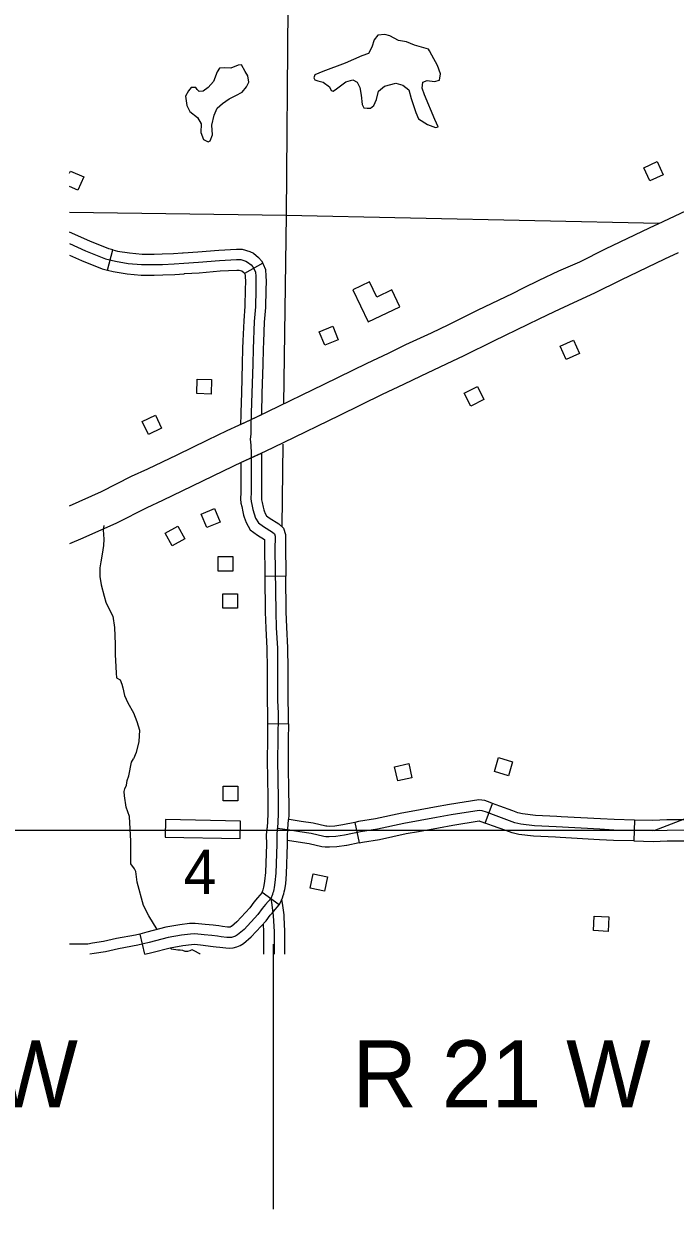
# Model space of a CAD drawing. Extents: x 61396 to 64680, y 55472 to 57605.
# Drawn here: x 61905.3 to 62051.4, y 55666.6 to 55932.3 of the extents above; entities that cross this region are included whole.
import ezdxf

# ---------------------------------------------------------------- set-up
doc = ezdxf.new("R2010")
doc.units = 0
for name, color, linetype in [('15', 7, 'Continuous'), ('31', 7, 'Continuous'), ('32', 7, 'Continuous'), ('35', 7, 'Continuous'), ('4', 7, 'Continuous'), ('5', 7, 'Continuous'), ('56', 7, 'Continuous'), ('57', 7, 'Continuous'), ('58', 7, 'Continuous'), ('Default', 7, 'Continuous'), ('R_Border Notes', 7, 'Continuous')]:
    doc.layers.add(name, color=color, linetype=linetype)

msp = doc.modelspace()

# ---------------------------------------------------------------- linework, layer by layer
at = {"layer": '15'}
for points in [[(61915.57, 55824.22), (61922.72, 55827.44), (61929.47, 55830.86), (61933.08, 55832.55), (61939.65, 55835.69), (61946.55, 55839.02), (61950.87, 55841.13), (61956.12, 55843.51), (61960.02, 55845.38), (61972.67, 55851.5), (61982.27, 55856.25), (61987.09, 55858.48), (61990.95, 55860.38), (61996.73, 55863.04), (62000.57, 55864.87), (62007.2, 55868.15), (62014.85, 55871.86), (62017.36, 55873.12), (62020.84, 55874.81), (62025.31, 55876.88), (62029.96, 55878.95), (62035.75, 55881.8), (62045.62, 55886.55), (62048.7, 55887.99), (62053.87, 55890.44)], [(62052.03, 55880.92), (62048.98, 55879.49), (62039.17, 55874.78), (62033.27, 55871.87), (62028.54, 55869.77), (62024.19, 55867.75), (62020.81, 55866.11), (62018.3, 55864.85), (62010.64, 55861.14), (62003.99, 55857.84), (62000.04, 55855.96), (61994.31, 55853.33), (61990.46, 55851.43), (61985.64, 55849.2), (61976.11, 55844.48), (61963.42, 55838.35), (61959.43, 55836.42), (61954.19, 55834.06), (61949.97, 55832), (61943.04, 55828.65), (61936.43, 55825.48), (61932.89, 55823.83), (61926.09, 55820.39), (61918.55, 55817), (61915.57, 55815.71)]]:
    msp.add_lwpolyline(points, dxfattribs=at)
at = {"layer": '31'}
for p, q in [((61924.07, 55877.07), (61925.22, 55881.61)), ((61924.07, 55877.07), (61924.07, 55877.07)), ((61958.86, 55878.64), (61954.77, 55876.34)), ((61953.94, 55833.94), (61958.63, 55836.06)), ((61964.03, 55808.47), (61959.34, 55808.42)), ((61959.95, 55775.48), (61964.63, 55775.43)), ((61964.63, 55775.43), (61964.63, 55775.43)), ((62008.79, 55753.15), (62010.43, 55757.55)), ((61979.56, 55753.32), (61980.53, 55748.73)), ((62042.21, 55753.84), (62042.1, 55749.15)), ((61962.52, 55734.83), (61958.74, 55737.62)), ((61931.3, 55728.3), (61932.38, 55723.76))]:
    msp.add_line(p, q, dxfattribs=at)
for points in [[(61925.22, 55881.61), (61924.34, 55881.83), (61920.08, 55883.54), (61915.57, 55885.59)], [(61915.57, 55883.01), (61919.16, 55881.39), (61923.61, 55879.6), (61925.82, 55879.04), (61928.73, 55878.58), (61931.71, 55878.3), (61934.51, 55878.3), (61936.37, 55878.34), (61939, 55878.44), (61941.17, 55878.62), (61944.47, 55878.83), (61949.2, 55879.21), (61953.02, 55879.42), (61953.93, 55879.42), (61955.09, 55879.07), (61955.48, 55878.86), (61956.28, 55878.23), (61956.63, 55877.81), (61956.95, 55877.25), (61957.26, 55876.59), (61957.3, 55875.71), (61957.33, 55874.52), (61957.3, 55872.66), (61957.23, 55868.84), (61956.95, 55865.55), (61956.7, 55859.45), (61956.63, 55856.01), (61956.42, 55849.49), (61956.31, 55845.09), (61956.23, 55842.25), (61956.2, 55841.99), (61956.2, 55841.16), (61956.17, 55840.28), (61956.09, 55839.2)], [(61915.57, 55880.44), (61918.24, 55879.23), (61922.89, 55877.37), (61924.07, 55877.07)], [(61925.22, 55881.61), (61926.29, 55881.34), (61929.02, 55880.91), (61931.82, 55880.65), (61934.49, 55880.65), (61936.3, 55880.68), (61938.86, 55880.78), (61940.86, 55880.94)], [(61940.86, 55880.94), (61941.01, 55880.96), (61944.3, 55881.17), (61949.04, 55881.55), (61952.96, 55881.77), (61954.28, 55881.77), (61956, 55881.25), (61956.77, 55880.83), (61957.92, 55879.92), (61958.57, 55879.15), (61958.86, 55878.64)], [(61924.07, 55877.07), (61925.35, 55876.74), (61928.44, 55876.26), (61931.6, 55875.96), (61934.54, 55875.96), (61936.44, 55875.99), (61939.14, 55876.1), (61941.24, 55876.27)], [(61941.24, 55876.27), (61941.34, 55876.28), (61944.64, 55876.49), (61949.36, 55876.88), (61953.09, 55877.08), (61953.59, 55877.08), (61954.18, 55876.9), (61954.18, 55876.9), (61954.64, 55876.54), (61954.69, 55876.48), (61954.77, 55876.34)], [(61959.11, 55861.02), (61959.29, 55865.4), (61959.57, 55868.72), (61959.64, 55872.62), (61959.68, 55874.53), (61959.64, 55875.79), (61959.59, 55877.16), (61959.03, 55878.33), (61958.86, 55878.64)], [(61954.77, 55876.34), (61954.86, 55876.17), (61954.94, 55876.01), (61954.96, 55875.63), (61954.99, 55874.51), (61954.95, 55872.7), (61954.89, 55868.96), (61954.61, 55865.69), (61954.43, 55861.21)], [(61954.43, 55861.21), (61954.36, 55859.52), (61954.29, 55856.07), (61954.08, 55849.56), (61953.97, 55845.15), (61953.96, 55844.69)], [(61958.65, 55844.72), (61958.66, 55845.03), (61958.76, 55849.43), (61958.97, 55855.95), (61959.04, 55859.38), (61959.11, 55861.02)], [(61953.96, 55844.69), (61953.9, 55842.5), (61956.12, 55843.51), (61958.65, 55844.72)], [(61956.09, 55839.2), (61956.21, 55837.87), (61956.28, 55835.96), (61956.28, 55832.57), (61956.28, 55827.22), (61956.24, 55825.87), (61956.31, 55825.24), (61956.45, 55824.54), (61956.67, 55823.44), (61956.94, 55822.42), (61957.28, 55821.52), (61957.89, 55820.43), (61959.03, 55819.59), (61961.09, 55818.35), (61961.49, 55817.98), (61961.65, 55817.48), (61961.62, 55814.41), (61961.67, 55809.81), (61961.78, 55800.48), (61961.91, 55796.93), (61962.16, 55792.34), (61962.19, 55788.15), (61962.22, 55780.59), (61962.31, 55777.8), (61962.25, 55771.83), (61962.22, 55767.34), (61962.34, 55758.6), (61962.37, 55755.08), (61962.18, 55751.92)], [(61958.63, 55836.06), (61958.63, 55832.57), (61958.63, 55827.18), (61958.58, 55825.96), (61958.62, 55825.61), (61958.75, 55825), (61958.96, 55823.97), (61959.12, 55823.37)], [(61953.94, 55833.94), (61953.94, 55832.57), (61953.94, 55827.26), (61953.89, 55825.78), (61953.99, 55824.87), (61954.16, 55824.07), (61954.39, 55822.92), (61954.58, 55822.18)], [(61954.58, 55822.18), (61954.7, 55821.71), (61955.15, 55820.53), (61956.09, 55818.84), (61957.73, 55817.64), (61959.3, 55816.7), (61959.28, 55814.41), (61959.33, 55809.78), (61959.34, 55808.42)], [(61959.12, 55823.37), (61959.18, 55823.14), (61959.41, 55822.51), (61959.69, 55822.02), (61960.33, 55821.55), (61962.51, 55820.23), (61963.54, 55819.28), (61963.99, 55817.83), (61963.96, 55814.42), (61964.02, 55809.84), (61964.03, 55808.47)], [(61959.34, 55808.42), (61959.44, 55800.42), (61959.57, 55796.83), (61959.82, 55792.27), (61959.82, 55791.94)], [(61964.51, 55791.97), (61964.5, 55792.41), (61964.25, 55797.04), (61964.12, 55800.53), (61964.03, 55808.47)], [(61959.82, 55791.94), (61959.85, 55788.14), (61959.88, 55780.55), (61959.97, 55777.78), (61959.95, 55775.48)], [(61964.63, 55775.43), (61964.66, 55777.83), (61964.57, 55780.64), (61964.54, 55788.16), (61964.51, 55791.97)], [(61959.95, 55775.48), (61959.91, 55771.85), (61959.88, 55767.33), (61960, 55758.93)], [(61964.63, 55775.43), (61964.6, 55771.81), (61964.57, 55767.34), (61964.68, 55758.99)], [(61960, 55758.93), (61960, 55758.57), (61960.03, 55755.14), (61959.84, 55752.06)], [(61964.68, 55758.99), (61964.69, 55758.62), (61964.72, 55755.01), (61964.65, 55753.94)], [(62010.43, 55757.55), (62009.84, 55757.77), (62008.66, 55758.21), (62007.33, 55758.37), (62000.72, 55757.34), (61997.42, 55756.71), (61993.01, 55755.92)], [(62025.81, 55754.59), (62024.79, 55754.65), (62020.01, 55754.88), (62017.13, 55755.25), (62016.09, 55755.49), (62014.99, 55755.88), (62012.01, 55756.96), (62010.43, 55757.55)], [(62056.34, 55751.56), (62049.53, 55751.52), (62046.38, 55751.4), (62037.62, 55751.6), (62034.5, 55751.76), (62024.67, 55752.31), (62019.8, 55752.55), (62016.72, 55752.94), (62015.44, 55753.23), (62014.2, 55753.68), (62011.2, 55754.76), (62009.02, 55755.57), (62008.1, 55755.91), (62007.37, 55756), (62001.11, 55755.03), (61997.85, 55754.41), (61990.55, 55753.09), (61984.62, 55751.79), (61980.81, 55751.19), (61977.24, 55750.43), (61975.29, 55750.14), (61973.8, 55750.08), (61973.04, 55750.1), (61972.57, 55750.16), (61969.74, 55750.84), (61967.17, 55751.22), (61964.96, 55751.54), (61962.18, 55751.92)], [(61993.01, 55755.92), (61990.08, 55755.39), (61984.18, 55754.09), (61980.38, 55753.49), (61979.56, 55753.32)], [(61964.44, 55749.24), (61964.42, 55750.31), (61964.52, 55751.76), (61964.65, 55753.94)], [(61976.82, 55752.74), (61975.07, 55752.47), (61973.78, 55752.42), (61973.22, 55752.44), (61972.99, 55752.47), (61970.19, 55753.14), (61967.51, 55753.54), (61965.28, 55753.86), (61964.65, 55753.94)], [(61979.56, 55753.32), (61976.82, 55752.74)], [(61993.84, 55751.3), (61998.28, 55752.11), (62001.51, 55752.72), (62007.41, 55753.64), (62007.54, 55753.62), (62008.2, 55753.38), (62008.79, 55753.15)], [(62025.54, 55749.91), (62024.54, 55749.97), (62019.59, 55750.21), (62016.32, 55750.63), (62014.78, 55750.98), (62013.4, 55751.47), (62010.39, 55752.56), (62008.79, 55753.15)], [(62042.21, 55753.84), (62037.7, 55753.94), (62034.63, 55754.1), (62025.81, 55754.59)], [(62058.81, 55753.61), (62058.2, 55753.66), (62056.51, 55753.9), (62049.48, 55753.86), (62046.36, 55753.75), (62042.21, 55753.84)], [(61958.74, 55737.62), (61958.92, 55738.03), (61958.98, 55738.23), (61959.06, 55738.5), (61959.13, 55738.82), (61959.22, 55739.2), (61959.37, 55740.11), (61959.55, 55742.11), (61959.76, 55748.43), (61959.73, 55750.42), (61959.84, 55752.07)], [(61960.74, 55736.35), (61961.13, 55737.21), (61961.24, 55737.59), (61961.33, 55737.92), (61961.41, 55738.29), (61961.52, 55738.75), (61961.69, 55739.81), (61961.89, 55741.97), (61962.11, 55748.41), (61962.08, 55750.37), (61962.18, 55751.92)], [(61980.53, 55748.73), (61981.24, 55748.88), (61985.05, 55749.48), (61991.01, 55750.79), (61993.84, 55751.3)], [(62042.1, 55749.15), (62037.53, 55749.26), (62034.38, 55749.42), (62025.54, 55749.91)], [(61962.52, 55734.83), (61962.88, 55735.39), (61963.33, 55736.39), (61963.49, 55736.96), (61963.6, 55737.34), (61963.7, 55737.76), (61963.82, 55738.3), (61964.02, 55739.52), (61964.23, 55741.82), (61964.45, 55748.39), (61964.44, 55749.24)], [(61977.73, 55748.14), (61977.65, 55748.12), (61975.51, 55747.8), (61973.81, 55747.73), (61972.86, 55747.76), (61972.15, 55747.85), (61969.29, 55748.53), (61966.83, 55748.91), (61964.44, 55749.24)], [(61980.53, 55748.73), (61977.73, 55748.14)], [(62042.1, 55749.15), (62046.39, 55749.06), (62049.58, 55749.18), (62056.18, 55749.21), (62057.68, 55748.99), (62058.46, 55748.94)], [(61960.74, 55736.35), (61959.5, 55734.91), (61958.72, 55734), (61957.81, 55732.71), (61954.68, 55729.35), (61953.21, 55728.09), (61952.77, 55727.84), (61952.32, 55727.65), (61951.86, 55727.52), (61951.46, 55727.5), (61950.8, 55727.52), (61949.54, 55727.67), (61948.7, 55727.79), (61947.44, 55727.94), (61945.74, 55728.14), (61943.67, 55728.34), (61942.68, 55728.29), (61940.62, 55728.04), (61937.65, 55727.52), (61933.44, 55726.41), (61930.83, 55725.78), (61926.54, 55724.96), (61923.6, 55724.34), (61921.09, 55723.92), (61920.12, 55723.76)], [(61958.74, 55737.62), (61957.73, 55736.43), (61956.87, 55735.44), (61955.99, 55734.19), (61953.06, 55731.04), (61951.85, 55730.01), (61951.74, 55729.95), (61951.54, 55729.87), (61951.48, 55729.85), (61951.44, 55729.85), (61950.97, 55729.86), (61949.84, 55729.99), (61949, 55730.11), (61948.34, 55730.19)], [(61947.79, 55725.54), (61948.4, 55725.46), (61949.24, 55725.34), (61950.63, 55725.18), (61951.48, 55725.16), (61952.25, 55725.19), (61953.1, 55725.44), (61953.81, 55725.73), (61954.57, 55726.17), (61956.31, 55727.65), (61959.64, 55731.23), (61960.57, 55732.55), (61961.28, 55733.38), (61962.52, 55734.83)], [(61931.3, 55728.3), (61930.34, 55728.08), (61926.08, 55727.26), (61923.16, 55726.64), (61920.7, 55726.23), (61919.67, 55726.06), (61919.13, 55726.06), (61917.7, 55726.03), (61916.55, 55726.04), (61915.58, 55726.05)], [(61948.34, 55730.19), (61947.72, 55730.26), (61945.99, 55730.47), (61943.72, 55730.69), (61942.47, 55730.63), (61940.28, 55730.36), (61937.14, 55729.81), (61932.87, 55728.68), (61931.3, 55728.3)], [(61915.58, 55726.05), (61915.57, 55726.05)], [(61932.44, 55723.76), (61934.01, 55724.13), (61938.15, 55725.23), (61940.97, 55725.72), (61942.88, 55725.95), (61943.62, 55725.99), (61945.49, 55725.81), (61947.16, 55725.61), (61947.79, 55725.54)]]:
    msp.add_lwpolyline(points, dxfattribs=at)
at = {"layer": '32'}
for points in [[(61961.49, 55723.76), (61961.49, 55728.87), (61961.32, 55732.41), (61960.99, 55734.84), (61960.74, 55736.35)], [(61963.68, 55732.07), (61963.65, 55732.63), (61963.3, 55735.19), (61963.17, 55736.03)], [(61963.84, 55723.76), (61963.84, 55728.93), (61963.68, 55732.07)], [(61959.15, 55723.76), (61959.15, 55728.81), (61959.06, 55730.61)]]:
    msp.add_lwpolyline(points, dxfattribs=at)
at = {"layer": '35'}
for points in [[(61996.03, 55926.6), (61992.91, 55927.5), (61991.08, 55928.21), (61989.35, 55928.53), (61987.38, 55929.55), (61986.28, 55929.86), (61984.71, 55929.71), (61983.84, 55928.68), (61983.37, 55927.03), (61982.58, 55925.61), (61981.09, 55925.06), (61977.39, 55923.41), (61972.36, 55921.6), (61970.55, 55920.82), (61970.31, 55920.19), (61970.55, 55919.71), (61971.26, 55919.48), (61972.44, 55919.16), (61973.85, 55918.14), (61974.24, 55917.35), (61974.64, 55917.2), (61975.43, 55917.67), (61977.47, 55919.24), (61979.04, 55919.71), (61980.07, 55919.16), (61980.62, 55917.98), (61980.93, 55916.25), (61981.17, 55914.21), (61981.56, 55913.42), (61982.27, 55913.34), (61983.06, 55913.34), (61983.76, 55913.97), (61984.39, 55915.31), (61984.87, 55917.2), (61986.2, 55918.3), (61988.72, 55918.93), (61990.3, 55918.53), (61991.63, 55917.43), (61992.18, 55915.55), (61993.21, 55912.4), (61993.84, 55910.98), (61995.8, 55909.72), (61997.61, 55909.02), (61998.24, 55909.17), (61997.46, 55910.83), (61995.17, 55916.33), (61994.62, 55917.83), (61994.78, 55919.16), (61995.72, 55919.56), (61997.38, 55919.32), (61998.48, 55919.64), (61998.71, 55921.05), (61998.08, 55922.94), (61996.83, 55925.22), (61996.27, 55926.17)], [(61954.94, 55921.61), (61954.09, 55923.08), (61953.35, 55923.02), (61951.75, 55922.34), (61950.4, 55922.41), (61949.18, 55922.34), (61948.69, 55921.49), (61947.83, 55919.34), (61946.6, 55917.99), (61945.5, 55917.13), (61944.58, 55917.07), (61944.15, 55917.56), (61943.84, 55917.99), (61942.86, 55917.99), (61942.24, 55917.25), (61941.57, 55916.03), (61941.88, 55913.94), (61942.49, 55912.59), (61944.21, 55911.3), (61945.07, 55909.83), (61945, 55907.87), (61945.62, 55906.33), (61946.6, 55905.84), (61947.09, 55906.03), (61947.58, 55907.38), (61947.46, 55909.58), (61948.01, 55911.79), (61948.69, 55913.33), (61949.85, 55914.43), (61951.32, 55915.47), (61952.86, 55916.21), (61954.27, 55916.95), (61955.25, 55918.11), (61955.74, 55919.15), (61955.56, 55920.57)]]:
    msp.add_lwpolyline(points, close=True, dxfattribs=at)
for points in [[(61923.24, 55819.85), (61923.12, 55818.85), (61923.27, 55816.75), (61923.19, 55815.36), (61922.83, 55813.42), (61922.54, 55811.69), (61922.36, 55810.33), (61922.35, 55808.39), (61922.65, 55806.54), (61923.3, 55803.97), (61923.72, 55802.69), (61924.2, 55801.56), (61925.23, 55799.5), (61925.63, 55797), (61925.76, 55793.26), (61925.81, 55790.91), (61925.9, 55788.15), (61925.98, 55786.73), (61926.08, 55785.67), (61926.9, 55785.27), (61927.29, 55784.3), (61927.52, 55783.45), (61927.88, 55781.76), (61928.62, 55780.08), (61929.86, 55777.86), (61930.63, 55775.89), (61931.21, 55774.01), (61931.05, 55771.44), (61930.48, 55768.95), (61929.87, 55767.52)], [(61935.23, 55729.26), (61935.21, 55729.29), (61933.31, 55732.41), (61932.15, 55734.68), (61930.68, 55739.94), (61930.38, 55742.33), (61930.1, 55742.93), (61929.3, 55744.01), (61929.26, 55745.34), (61929.26, 55749.14), (61928.98, 55754.67), (61928.26, 55756.76), (61927.9, 55759.28), (61927.82, 55760.24), (61927.98, 55760.84), (61928.3, 55761.65), (61928.46, 55762.69), (61928.82, 55763.73), (61929.46, 55766.81), (61929.87, 55767.52)], [(61944.83, 55723.76), (61944.76, 55723.84), (61943.53, 55724.54), (61943.01, 55724.76), (61942.8, 55724.67), (61942.49, 55724.51), (61942.03, 55724.39), (61941.51, 55724.39), (61940.99, 55724.64), (61940.35, 55724.7), (61939.8, 55724.7), (61938.45, 55724.94), (61938.12, 55725.22), (61938.09, 55725.24)]]:
    msp.add_lwpolyline(points, dxfattribs=at)
at = {"layer": '4'}
for points in [[(61964.47, 55935.98), (61964.12, 55889.4), (61963.53, 55847.01)], [(61963.4, 55838.09), (61963.15, 55819.64)]]:
    msp.add_lwpolyline(points, dxfattribs=at)
at = {"layer": '5'}
for points in [[(61915.57, 55890.03), (61964.12, 55889.4)], [(61964.12, 55889.4), (62047.74, 55887.59)]]:
    msp.add_lwpolyline(points, dxfattribs=at)
at = {"layer": '56'}
for points in [[(62045.71, 55897.05), (62044.34, 55900), (62047.29, 55901.38), (62048.67, 55898.43)], [(61972.8, 55860.22), (61971.56, 55863.23), (61974.57, 55864.48), (61975.82, 55861.47)], [(62026.95, 55857.05), (62025.59, 55860), (62028.55, 55861.37), (62029.92, 55858.41)], [(61944.07, 55849.39), (61944.16, 55852.64), (61947.42, 55852.55), (61947.33, 55849.3)], [(62005.54, 55846.61), (62004.08, 55849.52), (62007, 55850.98), (62008.46, 55848.07)], [(61933.24, 55840.22), (61931.84, 55843.16), (61934.79, 55844.56), (61936.18, 55841.62)], [(61946.32, 55819.36), (61945.07, 55822.36), (61948.08, 55823.62), (61949.33, 55820.62)], [(61938.53, 55815.27), (61936.96, 55818.12), (61939.83, 55819.69), (61941.39, 55816.84)], [(61948.89, 55809.62), (61948.89, 55812.88), (61952.15, 55812.88), (61952.15, 55809.62)], [(61949.95, 55801.31), (61949.95, 55804.56), (61953.21, 55804.56), (61953.21, 55801.31)], [(61989.15, 55762.61), (61988.45, 55765.78), (61991.63, 55766.49), (61992.34, 55763.32)], [(62010.83, 55764.71), (62011.78, 55767.82), (62014.9, 55766.86), (62013.95, 55763.75)], [(61950.01, 55758.16), (61950.01, 55761.42), (61953.28, 55761.42), (61953.28, 55758.16)], [(61969.52, 55738.58), (61970.19, 55741.76), (61973.38, 55741.09), (61972.71, 55737.91)], [(62033.05, 55729.06), (62033.21, 55732.31), (62036.47, 55732.15), (62036.31, 55728.9)]]:
    msp.add_lwpolyline(points, close=True, dxfattribs=at)
msp.add_lwpolyline([(61915.57, 55898.82), (61915.76, 55899.27), (61918.75, 55897.95), (61917.44, 55894.98), (61915.57, 55895.8)], dxfattribs=at)
at = {"layer": '57'}
for p, q in [((61937.06, 55753.93), (61936.99, 55750.03)), ((61953.85, 55753.62), (61937.06, 55753.93)), ((61953.78, 55749.72), (61953.85, 55753.62)), ((61936.99, 55750.03), (61953.78, 55749.72))]:
    msp.add_line(p, q, dxfattribs=at)
at = {"layer": '58'}
msp.add_lwpolyline([(61982.48, 55865.45), (61989.65, 55868.86), (61987.85, 55872.65), (61984.46, 55871.03), (61982.85, 55874.42), (61979.07, 55872.62)], close=True, dxfattribs=at)
at = {"layer": 'Default'}
for q in [(62762.7, 56029.16), (61571.46, 55751.5)]:
    msp.add_line((62046.64, 55751.5), q, dxfattribs=at)
at = {"layer": 'R_Border Notes'}
msp.add_line((61961.28, 55666.62), (61961.28, 55726.01), dxfattribs=at)

# ---------------------------------------------------------------- texts
at = {"layer": '57'}
msp.add_text('4', height=9.9, dxfattribs=at).set_placement((61941.13, 55737.28))
at = {"layer": 'R_Border Notes'}
for s, p in [('R 22 W', (61850.55, 55689.47)), ('R 21 W', (61978.97, 55689.47))]:
    msp.add_text(s, height=15, dxfattribs=at).set_placement(p)

doc.saveas('drawing.dxf')
